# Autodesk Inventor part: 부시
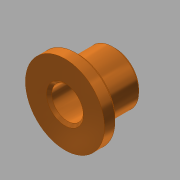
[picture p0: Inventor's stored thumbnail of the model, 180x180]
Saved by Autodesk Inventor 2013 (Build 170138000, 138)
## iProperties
Created: 2016-02
Part Number: 부시
Material: 스테인리스강
Document SubType Name: Modeling
Designer: mduedu
Density: 8.08 g/cm^3
Author: mduedu
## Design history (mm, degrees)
sketch "스케치1"
  geometry: C1 r 15 at (0, 0); 1 further point
  constraints: 1 centre point, 1 coincident
  dimensions: "d0" = 30 diameter of C1
extrude "돌출1" new body sketch "스케치1" distance "d1" = 5; taper "d2" = 0 deg
sketch "스케치2"
  geometry: C1 r 10 at (0, 0); 1 further point
  constraints: 1 centre point, 1 coincident
  dimensions: "d3" = 20 diameter of C1
extrude "돌출2" join sketch "스케치2" distance "d4" = 14; taper "d5" = 0 deg
hole "구멍1" diameter "d8" = 12; stored, may be unused: countersink angle "d12" = 90 deg, drill point angle "d14" = 118 deg; dims "d9" = 6, "d10" = 4, "d11" = 2, "d13" = 8, "d15" = 10, "d16" = 10
chamfer "모따기1" distance "d17" = 1; stored, may be unused: second distance "d18" = 2, angle "d19" = 45 deg
chamfer "모따기2" distance "d20" = 1; stored, may be unused: second distance "d21" = 2, angle "d22" = 45 deg
chamfer "모따기3" distance "d23" = 1; stored, may be unused: second distance "d24" = 2, angle "d25" = 45 deg
node "솔리드1"
